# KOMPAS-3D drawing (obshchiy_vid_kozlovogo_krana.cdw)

Referenced files in C:\Milord\: Чертеж.cdw
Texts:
  СДМ1-12.00.000 ВО
  Кран козловой общий вид
  Zver
  Microsoft
  Текст на чертеже
  Размерные надписи
  Шероховатость
  Линия-выноска #1
  Линия-выноска #2
  Линия-выноска #3
  Отклонения формы и база
  Заголовок таблицы
  Ячейка таблицы
  Стрелка вида
  Обозначение изменения
  Фигурная скобка
  Номер узла
  Марка координационной оси
  VRCB
  Выносная надпись
  Обозначение узла
  Марка/позиционное обозначение с линией-выноской
  Марка/позиционное обозначение на линии
  Марка/позиционное обозначение без линии-выноски
  Ошибки
  Ошибки размерных линий
  Техническая характеристика
  Грузоподьемность, Т                               10
  Пралет, м                                            20
  Высота подьема, м                                 8
  Длина моста, м                                   30000
  Ширина крана, м                                    10350
  Высота крана, м                                   10600
  Скорость (рабочая)
  подъема груза, м/мин                        10
  передвижения тележки, м/мин              16
  передвижения крана, м/мин                  20
  Масса, Т                                            28
  Схема запасовки
  а) каната механизма подъема груза
  б) каната механизма передвижения тележки
  на консоли
  тележка
  на крюковой подвеске
  Покраска кабины, корпуча крюковой подвески и внешних элементоа
  ходовой части крана в соответсктии с ГОСТ 12.2.058-81
  Технические требования
  СONTINUOUS_RGB_0_0_0_THICK_0.35
  СONTINUOUS_RGB_255_0_0_THICK_0.35
  СONTINUOUS_RGB_255_0_0_THICK_0.13
  СONTINUOUS_RGB_255_192_128_THICK_0.35
  СONTINUOUS_RGB_0_0_0_THICK_0.13
  POLYLINE_STYLE_0.18_RGB_0_0_0
  СONTINUOUS_RGB_0_64_255_THICK_0.35
  СONTINUOUS_RGB_255_255_0_THICK_0.35
  ACAD_ISO10W100_RGB_255_255_0_SC_1_THICK_0.13
  ACAD_ISO10W100_RGB_0_0_0_SC_1_THICK_0.13
  СONTINUOUS_RGB_80_80_0_THICK_0.15
  ACAD_ISO10W100_RGB_255_0_0_SC_1_THICK_0.13
  СONTINUOUS_RGB_0_255_255_THICK_0.35
  СONTINUOUS_RGB_0_255_0_THICK_0.35
  СONTINUOUS_RGB_255_64_0_THICK_0.35
  СONTINUOUS_RGB_80_80_0_THICK_0.35
  СONTINUOUS_RGB_0_0_0_THICK_0.15
  СONTINUOUS_RGB_0_0_255_THICK_0.35
  K5LT_AXLED_RGB_0_0_0_SC_1_THICK_0.13
  ACAD_ISO10W100_RGB_0_0_255_SC_1_THICK_0.13
  СONTINUOUS_RGB_0_0_255_THICK_0.15
  СONTINUOUS_RGB_0_0_255_THICK_0.13
  CONT_RGB_0_255_0_SC_1_THICK_0.18
  СONTINUOUS_RGB_0_0_0_THICK_0.3
  CONT_RGB_0_0_0_SC_1_THICK_0.18
  SACNCR
  MUDST
  Стили документа
  Кузьмич
  Передня
  Кран козловой
  общий вид
  СДМ1-12.00.000 ВО-
Dimensions and other numbers on the sheet: 7; 30000; 6000; 20000; 5800; 8000; 10600; 4000; 1; 2; 3; 4; 5; 6; 8; 9; 10; 11; 12; 2500; 16200; 1:75; 28 Т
